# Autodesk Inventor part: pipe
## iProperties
Author: Administrator
Shininess: 64.0
Angle Display Precision: 2
Document Length Units: 11272
Document Angle Units: 11286
Document Time Units: 11279
Document Mass Units: 11290
Document Length Units Precision: 3
Document Angle Units Precision: 2
Compacted: False
PropertySet Name: _Private Model Information
Created: 2001-10
Part Number: pipe
Document SubType Name: Modeling
Designer: Administrator
Control State: 0
Master: False
Checked Out: False
PropertySet Name: Design Tracking Control
Density: 0.0
Volumn: 0.0
Area: 0.0
PropertySet Name: Model Information
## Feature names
1. Extrusion1
